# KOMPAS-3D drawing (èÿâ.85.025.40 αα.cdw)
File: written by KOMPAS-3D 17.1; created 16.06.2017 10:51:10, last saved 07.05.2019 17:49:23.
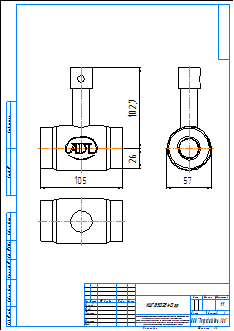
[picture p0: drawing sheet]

Sheet 1: A3, portrait

Title block, sheet 1: name: КШГ.85.025.40 рр; material: Внимание! Данный продукт является объектом авторского права ООО «Торговый Дом АДЛ». / Запрещается изменение, копирование, распространение / (в том числе путем копирования на другие сайты и ресурсы в Интернете) / или любое иное использование информации и объектов без предварительного / согласия правообладателя (ООО «Торговый Дом АДЛ»).; scale: 1:1; sheets: 1; organisation: ООО "Торговый дом АДЛ"; sheet format: A3; stored path: C:\Users\tra\Desktop\2д чертежи\Шаровые краны БИВАЛ\КШ_Бивал_серия_82_85\KOMPAS 2D\КШГ.85.025.40 рр.cdw

Views: Спереди 1, Проекционный вид 2, Проекционный вид 3
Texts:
  Klimkovich
  ADL
Dimensions and other numbers on the sheet: 105; 102,7; 26; 57; 1:1; 1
